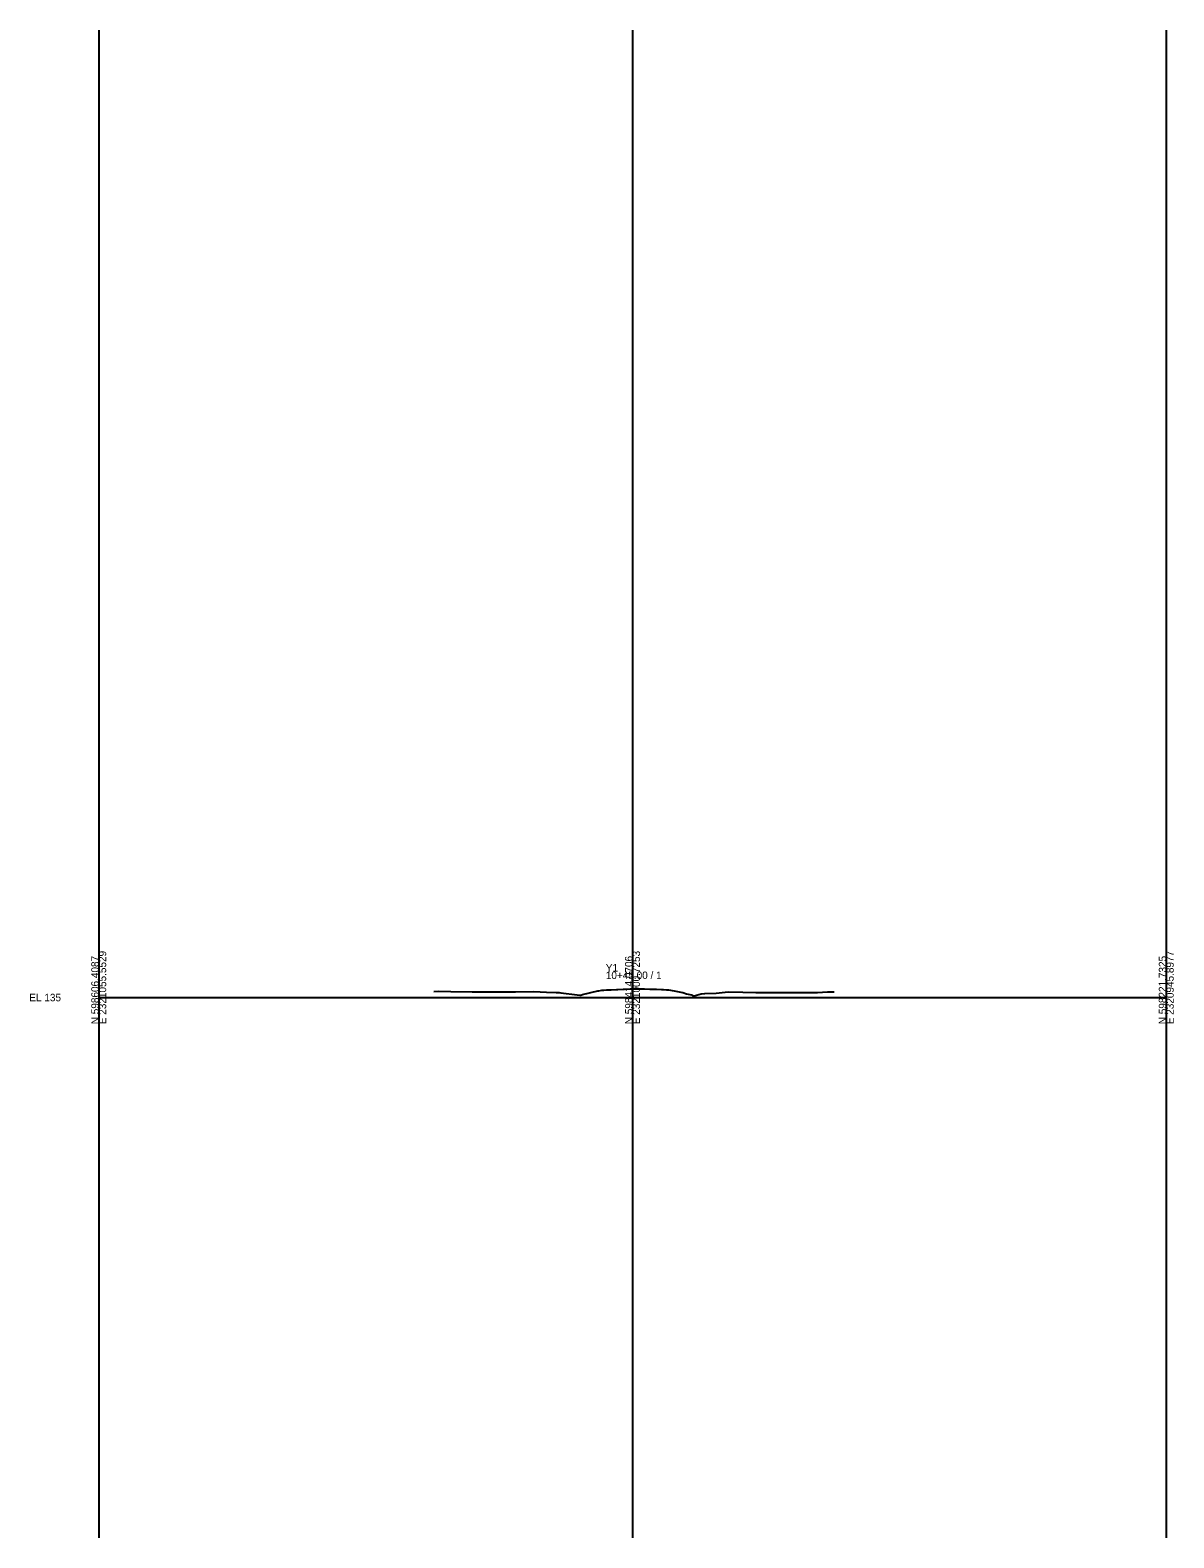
# Model space of a CAD drawing. Extents: x -26 to 2321974, y -203 to 598218.
# Drawn here: x 3374 to 3803, y -203 to 363 of the extents above; entities that cross this region are included whole.
import ezdxf

# ---------------------------------------------------------------- set-up
doc = ezdxf.new("R2010")
doc.units = 0
for name, color, linetype in [('Exist CMT Pavement', 7, 'Continuous'), ('Exist Cross Section Cell', 7, 'Continuous'), ('Exist XS Ground Line', 7, 'Continuous'), ('Prop XS Earthwork Shape', 7, 'Continuous'), ('Prop XS Exc Vertical Line 1', 7, 'Continuous'), ('Prop XS Exc Vertical Line 2', 7, 'Continuous'), ('Prop XS Exc Vertical Line 3', 7, 'Continuous')]:
    doc.layers.add(name, color=color, linetype=linetype)

msp = doc.modelspace()

# ---------------------------------------------------------------- linework, layer by layer
at = {"layer": 'Exist CMT Pavement'}
for points in [[(3599.9, 3.23), (3599.9, 3.33), (3600, 3.33), (3600, 3.23)], [(3600, 3.23), (3600, 3.33), (3600.1, 3.33), (3600.1, 3.23)]]:
    msp.add_lwpolyline(points, dxfattribs=at)
at = {"layer": 'Exist Cross Section Cell'}
for p, q in [((3600, 0), (3600, 9.74)), ((3400, 0), (3600, 0)), ((3600, 0), (3800, 0))]:
    msp.add_line(p, q, dxfattribs=at)
at = {"layer": 'Exist XS Ground Line'}
msp.add_lwpolyline([(3525.5, 2.31), (3527.28, 2.37), (3531.88, 2.28), (3539.93, 2.15), (3542.23, 2.14), (3548.03, 2.17), (3552.63, 2.09), (3556.12, 2.08), (3563.03, 2.25), (3567.78, 2), (3571.44, 1.91), (3572.49, 1.85), (3573.1, 1.76), (3579.28, 1.02), (3580.21, 0.91), (3580.59, 0.93), (3581.32, 1.12), (3587.05, 2.5), (3587.44, 2.57), (3588.49, 2.74), (3589.31, 2.81), (3590.31, 2.86), (3590.63, 2.87), (3591.47, 2.91), (3592.02, 2.94), (3593.97, 3.02), (3594.53, 3.04), (3596.47, 3.12), (3597.04, 3.14), (3599.12, 3.21), (3600, 3.23), (3600.47, 3.24), (3601.47, 3.24), (3602.06, 3.23), (3603.97, 3.21), (3604.56, 3.2), (3606.47, 3.18), (3607.07, 3.16), (3608.97, 3.13), (3610.85, 3.07), (3611.65, 3.06), (3612.73, 2.94), (3613.51, 2.9), (3615.63, 2.46), (3618.05, 1.96), (3618.84, 1.83), (3620.2, 1.42), (3622.15, 1.02), (3622.44, 0.72), (3623.14, 0.69), (3623.99, 0.9), (3625.71, 1.36), (3627.13, 1.56), (3631.34, 1.64), (3634.69, 1.99), (3635.83, 2.13), (3641.33, 2.01), (3646.23, 1.92), (3648.18, 1.91), (3656.62, 1.93), (3662.73, 1.9), (3666.77, 1.9), (3669.34, 1.92), (3673.1, 2.12), (3674.71, 2.12), (3675.6, 2.19)], dxfattribs=at)
at = {"layer": 'Prop XS Earthwork Shape'}
msp.add_lwpolyline([(3599.9, 3.23), (3600, 3.23), (3600, 3.33), (3599.9, 3.33)], close=True, dxfattribs=at)
msp.add_lwpolyline([(3599.9, 3.23), (3600, 3.23), (3600, 3.33), (3599.9, 3.33)], close=True, dxfattribs=at)
msp.add_lwpolyline([(3599.9, 3.23), (3600, 3.23), (3600, 3.33), (3599.9, 3.33)], close=True, dxfattribs=at)
msp.add_lwpolyline([(3599.9, 3.23), (3600, 3.23), (3600, 3.33), (3599.9, 3.33)], close=True, dxfattribs=at)
msp.add_lwpolyline([(3599.9, 3.23), (3600, 3.23), (3600, 3.33), (3599.9, 3.33)], close=True, dxfattribs=at)
at = {"layer": 'Prop XS Exc Vertical Line 1'}
msp.add_line((3400, 362.59), (3400, -202.52), dxfattribs=at)
at = {"layer": 'Prop XS Exc Vertical Line 2'}
msp.add_line((3600, 362.59), (3600, -202.52), dxfattribs=at)
at = {"layer": 'Prop XS Exc Vertical Line 3'}
msp.add_line((3800, 362.59), (3800, -202.52), dxfattribs=at)

# ---------------------------------------------------------------- texts
at = {"layer": 'Exist Cross Section Cell'}
for s, p in [('E 2321055.5529', (3402.8, -10)), ('E 2321000.7253', (3602.8, -10)), ('E 2320945.8977', (3802.8, -10)), ('N 598606.4087', (3400, -10)), ('N 598414.0706', (3600, -10)), ('N 598221.7325', (3800, -10))]:
    msp.add_text(s, height=2.8, rotation=90, dxfattribs=at).set_placement(p)
for s, p in [('Y1', (3590, 9.74)), ('10+45.00 / 1', (3590, 6.94)), ('EL 135', (3374, -1.4))]:
    msp.add_text(s, height=2.8, dxfattribs=at).set_placement(p)

doc.saveas('drawing.dxf')
